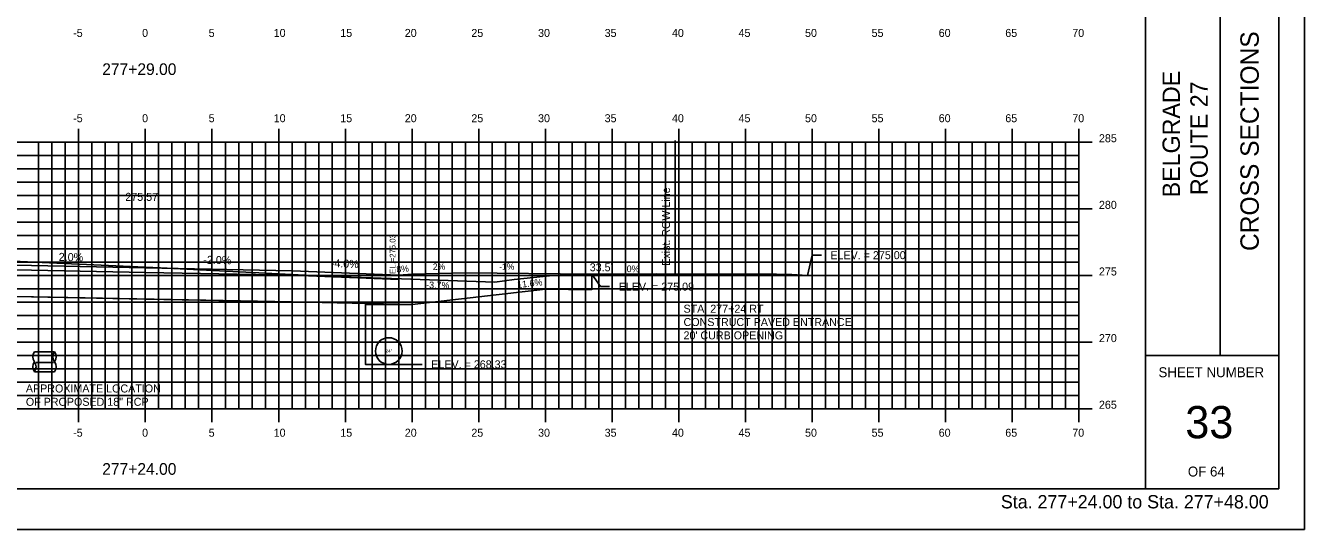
# Model space of a CAD drawing. Extents: x 854231 to 854401, y 366268 to 366378.
# Drawn here: x 854304.8 to 854400.7, y 366268.2 to 366306 of the extents above; entities that cross this region are included whole.
import ezdxf

# ---------------------------------------------------------------- set-up
doc = ezdxf.new("R2010")
doc.units = 0
for name, color, linetype in [('ANNOTATION', 7, 'Continuous'), ('BORDER', 7, 'Continuous'), ('D_Drainage_Culvert', 7, 'Continuous'), ('D_Drainage_Text', 7, 'Continuous'), ('D_Roadway_Centerline_Text', 7, 'Continuous'), ('D_Roadway_Drive_Gravel_RT', 7, 'Continuous'), ('D_Roadway_Drive_SubGrade', 7, 'Continuous'), ('D_Roadway_Edge_TW', 7, 'Continuous'), ('D_Roadway_SubGrade', 7, 'Continuous'), ('D_Text_Monospaced', 7, 'Continuous'), ('D_Text_Standard', 7, 'Continuous'), ('E_ROW_Line', 7, 'Continuous'), ('H_V ANNOTATION', 7, 'Continuous'), ('HIGHWAY_TITLE', 7, 'Continuous'), ('JUNK COM EXC', 7, 'Continuous'), ('junk strct exc', 7, 'Continuous'), ('MAJOR', 7, 'Continuous'), ('MINOR', 7, 'Continuous'), ('PDRAIN', 7, 'Continuous'), ('PLOT BOUNDARY', 7, 'Continuous'), ('S_Roadway_Centerline', 7, 'Continuous')]:
    doc.layers.add(name, color=color, linetype=linetype)

msp = doc.modelspace()

# ---------------------------------------------------------------- linework, layer by layer
at = {"layer": 'ANNOTATION'}
msp.add_line((854305.588, 366280.717), (854306.899, 366280.717), dxfattribs=at)
at = {"layer": 'BORDER'}
for p, q in [((854388.771, 366271.236), (854388.771, 366376.239)), ((854398.771, 366271.236), (854398.771, 366376.236)), ((854394.362, 366281.239), (854394.362, 366316.239)), ((854388.771, 366281.239), (854398.771, 366281.239)), ((854238.771, 366271.236), (854398.771, 366271.236))]:
    msp.add_line(p, q, dxfattribs=at)
at = {"layer": 'D_Drainage_Culvert'}
for p, q in [((854306.966, 366281.514), (854305.466, 366281.514)), ((854306.966, 366280.014), (854305.466, 366280.014))]:
    msp.add_line(p, q, dxfattribs=at)
for centre, radius, start, end in [((854305.966, 366281.139), 0.625, 143.1301, 216.8699), ((854307.466, 366281.139), 0.625, 143.1301, 216.8699), ((854306.466, 366281.139), 0.625, 323.1301, 36.8699), ((854305.966, 366280.389), 0.625, 143.1301, 216.8699), ((854304.892, 366280.389), 0.685, 326.80754, 33.19246), ((854306.466, 366280.389), 0.625, 323.1301, 36.8699)]:
    msp.add_arc(centre, radius, start, end, dxfattribs=at)
at = {"layer": 'D_Roadway_Drive_Gravel_RT'}
for p, q in [((854332.77, 366287.263), (854333.77, 366287.343)), ((854332.774, 366286.93), (854332.774, 366287.264)), ((854333.77, 366287.343), (854337.77, 366287.423)), ((854337.77, 366287.423), (854347.249, 366287.328)), ((854343.771, 366286.196), (854347.237, 366286.162))]:
    msp.add_line(p, q, dxfattribs=at)
at = {"layer": 'D_Roadway_Drive_SubGrade'}
for p, q in [((854347.249, 366287.328), (854347.249, 366286.162)), ((854333.774, 366285.07), (854343.771, 366286.196)), ((854332.774, 366285.09), (854333.774, 366285.07))]:
    msp.add_line(p, q, dxfattribs=at)
at = {"layer": 'D_Roadway_Edge_TW'}
msp.add_lwpolyline([(854294.774, 366287.703), (854302.774, 366288.023), (854324.774, 366287.583), (854332.77, 366287.263)], dxfattribs=at)
at = {"layer": 'D_Roadway_SubGrade'}
for points in [[(854302.774, 366285.69), (854302.774, 366287.69), (854313.774, 366287.47), (854324.774, 366287.25), (854324.774, 366285.25), (854313.774, 366285.47)], [(854324.774, 366287.25), (854332.774, 366286.93), (854332.774, 366285.09), (854324.774, 366285.25)]]:
    msp.add_lwpolyline(points, close=True, dxfattribs=at)
at = {"layer": 'D_Text_Standard'}
for points in [[(854363.418, 366287.232), (854363.778, 366288.759), (854364.458, 366288.759)], [(854347.249, 366287.328), (854347.906, 366286.397), (854348.586, 366286.397)], [(854333.774, 366280.566), (854333.851, 366280.566), (854334.531, 366280.566)]]:
    msp.add_lwpolyline(points, dxfattribs=at)
at = {"layer": 'E_ROW_Line'}
msp.add_line((854353.509, 366287.362), (854353.509, 366297.362), dxfattribs=at)
at = {"layer": 'JUNK COM EXC'}
msp.add_lwpolyline([(854293.772, 366288.043), (854293.774, 366285.51), (854302.774, 366285.69), (854324.774, 366285.25), (854333.774, 366285.07), (854333.77, 366286.951), (854332.973, 366286.981), (854327.686, 366287.169), (854318.367, 366287.641), (854314.902, 366287.816), (854313.222, 366287.894), (854303.833, 366288.299), (854294.211, 366288.049), (854293.772, 366288.043)], dxfattribs=at)
at = {"layer": 'junk strct exc'}
msp.add_lwpolyline([(854330.274, 366285.07), (854330.274, 366280.566), (854333.774, 366280.566), (854333.774, 366285.07)], close=True, dxfattribs=at)
at = {"layer": 'MAJOR'}
for p, q in [((854308.771, 366298.238), (854308.771, 366297.236)), ((854313.771, 366298.238), (854313.771, 366297.236)), ((854318.771, 366298.238), (854318.771, 366297.236)), ((854323.771, 366298.238), (854323.771, 366297.236)), ((854328.771, 366298.238), (854328.771, 366297.236)), ((854333.771, 366298.238), (854333.771, 366297.236)), ((854338.771, 366298.238), (854338.771, 366297.236)), ((854343.771, 366298.238), (854343.771, 366297.236)), ((854348.771, 366298.238), (854348.771, 366297.236)), ((854353.771, 366298.238), (854353.771, 366297.236)), ((854358.771, 366298.238), (854358.771, 366297.236)), ((854363.771, 366298.238), (854363.771, 366297.236)), ((854368.771, 366298.238), (854368.771, 366297.236)), ((854373.771, 366298.238), (854373.771, 366297.236)), ((854378.771, 366298.238), (854378.771, 366297.236)), ((854383.771, 366298.238), (854383.771, 366297.236)), ((854243.771, 366297.236), (854383.771, 366297.236)), ((854243.771, 366297.236), (854383.771, 366297.236)), ((854308.771, 366277.236), (854308.771, 366297.236)), ((854313.771, 366277.236), (854313.771, 366297.236)), ((854318.771, 366277.236), (854318.771, 366297.236)), ((854323.771, 366277.236), (854323.771, 366297.236)), ((854328.771, 366277.236), (854328.771, 366297.236)), ((854333.771, 366277.236), (854333.771, 366297.236)), ((854338.771, 366277.236), (854338.771, 366297.236)), ((854343.771, 366277.236), (854343.771, 366297.236)), ((854348.771, 366277.236), (854348.771, 366297.236)), ((854353.771, 366277.236), (854353.771, 366297.236)), ((854358.771, 366277.236), (854358.771, 366297.236)), ((854363.771, 366277.236), (854363.771, 366297.236)), ((854368.771, 366277.236), (854368.771, 366297.236)), ((854373.771, 366277.236), (854373.771, 366297.236)), ((854378.771, 366277.236), (854378.771, 366297.236)), ((854384.773, 366297.236), (854382.769, 366297.236)), ((854383.771, 366277.236), (854383.771, 366297.236)), ((854383.771, 366277.236), (854383.771, 366297.236)), ((854243.771, 366292.236), (854383.771, 366292.236)), ((854384.773, 366292.236), (854382.769, 366292.236)), ((854243.771, 366287.236), (854383.771, 366287.236)), ((854384.773, 366287.236), (854382.769, 366287.236)), ((854243.771, 366282.236), (854383.771, 366282.236)), ((854384.773, 366282.236), (854382.769, 366282.236)), ((854243.771, 366277.236), (854383.771, 366277.236)), ((854243.771, 366277.236), (854383.771, 366277.236)), ((854308.771, 366276.234), (854308.771, 366277.236)), ((854313.771, 366276.234), (854313.771, 366277.236)), ((854318.771, 366276.234), (854318.771, 366277.236)), ((854323.771, 366276.234), (854323.771, 366277.236)), ((854328.771, 366276.234), (854328.771, 366277.236)), ((854333.771, 366276.234), (854333.771, 366277.236)), ((854338.771, 366276.234), (854338.771, 366277.236)), ((854343.771, 366276.234), (854343.771, 366277.236)), ((854348.771, 366276.234), (854348.771, 366277.236)), ((854353.771, 366276.234), (854353.771, 366277.236)), ((854358.771, 366276.234), (854358.771, 366277.236)), ((854363.771, 366276.234), (854363.771, 366277.236)), ((854368.771, 366276.234), (854368.771, 366277.236)), ((854373.771, 366276.234), (854373.771, 366277.236)), ((854378.771, 366276.234), (854378.771, 366277.236)), ((854384.773, 366277.236), (854382.769, 366277.236)), ((854383.771, 366276.234), (854383.771, 366277.236))]:
    msp.add_line(p, q, dxfattribs=at)
at = {"layer": 'MINOR'}
for p, q in [((854305.771, 366277.236), (854305.771, 366297.236)), ((854306.771, 366277.236), (854306.771, 366297.236)), ((854306.771, 366277.236), (854306.771, 366297.236)), ((854307.771, 366277.236), (854307.771, 366297.236)), ((854309.771, 366277.236), (854309.771, 366297.236)), ((854310.771, 366277.236), (854310.771, 366297.236)), ((854311.771, 366277.236), (854311.771, 366297.236)), ((854312.771, 366277.236), (854312.771, 366297.236)), ((854314.771, 366277.236), (854314.771, 366297.236)), ((854315.771, 366277.236), (854315.771, 366297.236)), ((854316.771, 366277.236), (854316.771, 366297.236)), ((854317.771, 366277.236), (854317.771, 366297.236)), ((854319.771, 366277.236), (854319.771, 366297.236)), ((854320.771, 366277.236), (854320.771, 366297.236)), ((854321.771, 366277.236), (854321.771, 366297.236)), ((854322.771, 366277.236), (854322.771, 366297.236)), ((854324.771, 366277.236), (854324.771, 366297.236)), ((854325.771, 366277.236), (854325.771, 366297.236)), ((854326.771, 366277.236), (854326.771, 366297.236)), ((854327.771, 366277.236), (854327.771, 366297.236)), ((854329.771, 366277.236), (854329.771, 366297.236)), ((854330.771, 366277.236), (854330.771, 366297.236)), ((854331.771, 366277.236), (854331.771, 366297.236)), ((854332.771, 366277.236), (854332.771, 366297.236)), ((854334.771, 366277.236), (854334.771, 366297.236)), ((854335.771, 366277.236), (854335.771, 366297.236)), ((854336.771, 366277.236), (854336.771, 366297.236)), ((854337.771, 366277.236), (854337.771, 366297.236)), ((854339.771, 366277.236), (854339.771, 366297.236)), ((854340.771, 366277.236), (854340.771, 366297.236)), ((854341.771, 366277.236), (854341.771, 366297.236)), ((854342.771, 366277.236), (854342.771, 366297.236)), ((854344.771, 366277.236), (854344.771, 366297.236)), ((854345.771, 366277.236), (854345.771, 366297.236)), ((854346.771, 366277.236), (854346.771, 366297.236)), ((854347.771, 366277.236), (854347.771, 366297.236)), ((854349.771, 366277.236), (854349.771, 366297.236)), ((854350.771, 366277.236), (854350.771, 366297.236)), ((854351.771, 366277.236), (854351.771, 366297.236)), ((854352.771, 366277.236), (854352.771, 366297.236)), ((854354.771, 366277.236), (854354.771, 366297.236)), ((854355.771, 366277.236), (854355.771, 366297.236)), ((854356.771, 366277.236), (854356.771, 366297.236)), ((854357.771, 366277.236), (854357.771, 366297.236)), ((854359.771, 366277.236), (854359.771, 366297.236)), ((854360.771, 366277.236), (854360.771, 366297.236)), ((854361.771, 366277.236), (854361.771, 366297.236)), ((854362.771, 366277.236), (854362.771, 366297.236)), ((854364.771, 366277.236), (854364.771, 366297.236)), ((854365.771, 366277.236), (854365.771, 366297.236)), ((854366.771, 366277.236), (854366.771, 366297.236)), ((854367.771, 366277.236), (854367.771, 366297.236)), ((854369.771, 366277.236), (854369.771, 366297.236)), ((854370.771, 366277.236), (854370.771, 366297.236)), ((854371.771, 366277.236), (854371.771, 366297.236)), ((854372.771, 366277.236), (854372.771, 366297.236)), ((854374.771, 366277.236), (854374.771, 366297.236)), ((854375.771, 366277.236), (854375.771, 366297.236)), ((854376.771, 366277.236), (854376.771, 366297.236)), ((854377.771, 366277.236), (854377.771, 366297.236)), ((854379.771, 366277.236), (854379.771, 366297.236)), ((854380.771, 366277.236), (854380.771, 366297.236)), ((854381.771, 366277.236), (854381.771, 366297.236)), ((854382.771, 366277.236), (854382.771, 366297.236)), ((854243.771, 366296.236), (854383.771, 366296.236)), ((854383.771, 366296.236), (854382.769, 366296.236)), ((854243.771, 366295.236), (854383.771, 366295.236)), ((854383.771, 366295.236), (854382.769, 366295.236)), ((854243.771, 366294.236), (854383.771, 366294.236)), ((854383.771, 366294.236), (854382.769, 366294.236)), ((854243.771, 366293.236), (854383.771, 366293.236)), ((854383.771, 366293.236), (854382.769, 366293.236)), ((854243.771, 366291.236), (854383.771, 366291.236)), ((854383.771, 366291.236), (854382.769, 366291.236)), ((854243.771, 366290.236), (854383.771, 366290.236)), ((854383.771, 366290.236), (854382.769, 366290.236)), ((854243.771, 366289.236), (854383.771, 366289.236)), ((854383.771, 366289.236), (854382.769, 366289.236)), ((854243.771, 366288.236), (854383.771, 366288.236)), ((854383.771, 366288.236), (854382.769, 366288.236)), ((854243.771, 366286.236), (854383.771, 366286.236)), ((854383.771, 366286.236), (854382.769, 366286.236)), ((854243.771, 366285.236), (854383.771, 366285.236)), ((854383.771, 366285.236), (854382.769, 366285.236)), ((854243.771, 366284.236), (854383.771, 366284.236)), ((854383.771, 366284.236), (854382.769, 366284.236)), ((854243.771, 366283.236), (854383.771, 366283.236)), ((854383.771, 366283.236), (854382.769, 366283.236)), ((854243.771, 366281.236), (854383.771, 366281.236)), ((854383.771, 366281.236), (854382.769, 366281.236)), ((854243.771, 366280.236), (854383.771, 366280.236)), ((854383.771, 366280.236), (854382.769, 366280.236)), ((854243.771, 366279.236), (854383.771, 366279.236)), ((854383.771, 366279.236), (854382.769, 366279.236)), ((854243.771, 366278.236), (854383.771, 366278.236)), ((854383.771, 366278.236), (854382.769, 366278.236))]:
    msp.add_line(p, q, dxfattribs=at)
at = {"layer": 'PDRAIN'}
msp.add_lwpolyline([(854330.274, 366285.14), (854330.274, 366280.566), (854333.774, 366280.566), (854333.774, 366285.07)], dxfattribs=at)
msp.add_circle((854332.024, 366281.566), 1, dxfattribs=at)
at = {"layer": 'PLOT BOUNDARY'}
msp.add_lwpolyline([(854230.678, 366268.177), (854400.678, 366268.177), (854400.678, 366378.177), (854230.678, 366378.177)], close=True, dxfattribs=at)
at = {"layer": 'S_Roadway_Centerline'}
msp.add_lwpolyline([(854303.833, 366288.299), (854313.222, 366287.894), (854314.902, 366287.816), (854318.367, 366287.641), (854327.686, 366287.169), (854332.973, 366286.981), (854339.984, 366286.724), (854341.439, 366286.923), (854344.319, 366287.228), (854346.684, 366287.324), (854352.088, 366287.37), (854361.09, 366287.323), (854362.245, 366287.298), (854363.418, 366287.232)], dxfattribs=at)

# ---------------------------------------------------------------- texts
at = {"layer": 'ANNOTATION'}
for s, rotation, p in [('2.0%', 358.85423, (854307.277, 366288.334)), ('-2.0%', 358.85423, (854318.117, 366288.117)), ('-4.0%', 357.70942, (854327.667, 366287.869))]:
    msp.add_text(s, height=0.6, rotation=rotation, dxfattribs=at).set_placement(p)
for s, p in [('STA. 277+24 RT', (854354.125, 366284.441)), ('CONSTRUCT PAVED ENTRANCE', (854354.125, 366283.441)), ("20' CURB OPENING", (854354.125, 366282.441))]:
    msp.add_text(s, height=0.6, dxfattribs=at).set_placement(p)
at = {"layer": 'BORDER'}
for s, height, rotation, p in [('CROSS SECTIONS', 1.37787, 90, (854397.255, 366289.073)), ('SHEET NUMBER', 0.74527, 360, (854389.736, 366279.603)), ('33', 2.4194, 360, (854391.747, 366275.019)), ('OF 64', 0.7453, 360, (854391.938, 366272.149))]:
    msp.add_text(s, height=height, rotation=rotation, dxfattribs=at).set_placement(p)
at = {"layer": 'D_Drainage_Text'}
for s, p in [('APPROXIMATE LOCATION', (854304.815, 366278.456)), ('OF PROPOSED 18" RCP', (854304.815, 366277.456))]:
    msp.add_text(s, height=0.6, dxfattribs=at).set_placement(p)
at = {"layer": 'D_Roadway_Centerline_Text'}
msp.add_text('275.57', height=0.6, dxfattribs=at).set_placement((854312.272, 366292.835))
at = {"layer": 'D_Roadway_Drive_Gravel_RT'}
for s, rotation, p in [('8%', 4.57392, (854332.617, 366287.457)), ('2%', 1.19222, (854335.332, 366287.652))]:
    msp.add_text(s, height=0.48, rotation=rotation, dxfattribs=at).set_placement(p)
msp.add_text('-1%', height=0.48, dxfattribs=at).set_placement((854340.299, 366287.663))
at = {"layer": 'D_Text_Monospaced'}
for s, rotation, p in [('0%', 359.62651, (854349.861, 366287.486)), ('11.6%', 6.2166, (854341.681, 366286.289)), ('-3.7%', 358.69433, (854334.824, 366286.286))]:
    msp.add_text(s, height=0.5, rotation=rotation, dxfattribs=at).set_placement(p)
at = {"layer": 'D_Text_Standard'}
msp.add_text(' EL.=275.03', height=0.4335, rotation=90, dxfattribs=at).set_placement((854332.528, 366287.194))
for s, p in [('ELEV. = 275.00', (854365.138, 366288.459)), ("33.5'", (854347.093, 366287.551)), ('ELEV. = 275.09', (854349.266, 366286.097)), ('ELEV. = 268.33', (854335.211, 366280.266))]:
    msp.add_text(s, height=0.6, dxfattribs=at).set_placement(p)
at = {"layer": 'E_ROW_Line'}
msp.add_text('Exist. ROW Line', height=0.6, rotation=90, dxfattribs=at).set_placement((854353.109, 366287.962))
at = {"layer": 'H_V ANNOTATION'}
for s, height, p in [('-5', 0.6, (854308.361, 366305.136)), ('0', 0.6, (854313.53, 366305.136)), ('5', 0.6, (854318.522, 366305.136)), ('10', 0.6, (854323.396, 366305.136)), ('15', 0.6, (854328.388, 366305.136)), ('20', 0.6, (854333.225, 366305.136)), ('25', 0.6, (854338.217, 366305.136)), ('30', 0.6, (854343.219, 366305.136)), ('35', 0.6, (854348.211, 366305.136)), ('40', 0.6, (854353.257, 366305.136)), ('45', 0.6, (854358.249, 366305.136)), ('50', 0.6, (854363.235, 366305.136)), ('55', 0.6, (854368.227, 366305.136)), ('60', 0.6, (854373.257, 366305.136)), ('65', 0.6, (854378.249, 366305.136)), ('70', 0.6, (854383.273, 366305.136)), ('277+29.00', 0.875, (854310.54, 366302.28)), ('-5', 0.6, (854308.361, 366298.736)), ('0', 0.6, (854313.53, 366298.736)), ('5', 0.6, (854318.522, 366298.736)), ('10', 0.6, (854323.396, 366298.736)), ('15', 0.6, (854328.388, 366298.736)), ('20', 0.6, (854333.225, 366298.736)), ('25', 0.6, (854338.217, 366298.736)), ('30', 0.6, (854343.219, 366298.736)), ('35', 0.6, (854348.211, 366298.736)), ('40', 0.6, (854353.257, 366298.736)), ('45', 0.6, (854358.249, 366298.736)), ('50', 0.6, (854363.235, 366298.736)), ('55', 0.6, (854368.227, 366298.736)), ('60', 0.6, (854373.257, 366298.736)), ('65', 0.6, (854378.249, 366298.736)), ('70', 0.6, (854383.273, 366298.736)), ('285', 0.6, (854385.271, 366297.236)), ('280', 0.6, (854385.271, 366292.236)), ('275', 0.6, (854385.271, 366287.236)), ('270', 0.6, (854385.271, 366282.236)), ('265', 0.6, (854385.271, 366277.236)), ('-5', 0.6, (854308.361, 366275.136)), ('0', 0.6, (854313.53, 366275.136)), ('5', 0.6, (854318.522, 366275.136)), ('10', 0.6, (854323.396, 366275.136)), ('15', 0.6, (854328.388, 366275.136)), ('20', 0.6, (854333.225, 366275.136)), ('25', 0.6, (854338.217, 366275.136)), ('30', 0.6, (854343.219, 366275.136)), ('35', 0.6, (854348.211, 366275.136)), ('40', 0.6, (854353.257, 366275.136)), ('45', 0.6, (854358.249, 366275.136)), ('50', 0.6, (854363.235, 366275.136)), ('55', 0.6, (854368.227, 366275.136)), ('60', 0.6, (854373.257, 366275.136)), ('65', 0.6, (854378.249, 366275.136)), ('70', 0.6, (854383.273, 366275.136)), ('277+24.00', 0.875, (854310.54, 366272.28)), ('Sta. 277+24.00 to Sta. 277+48.00', 1.0002, (854377.917, 366269.756))]:
    msp.add_text(s, height=height, dxfattribs=at).set_placement(p)
at = {"layer": 'HIGHWAY_TITLE'}
for s, p in [('BELGRADE', (854391.343, 366293.095)), ('ROUTE 27', (854393.43, 366293.269))]:
    msp.add_text(s, height=1.3043, rotation=90, dxfattribs=at).set_placement(p)
at = {"layer": 'PDRAIN'}
msp.add_text('24"', height=0.25, dxfattribs=at).set_placement((854331.782, 366281.441))
at = {"layer": 'S_Roadway_Centerline'}
for s, p in [('C', (854314.897, 366287.816)), ('L', (854314.902, 366287.809))]:
    msp.add_text(s, height=0.0146, dxfattribs=at).set_placement(p)

doc.saveas('drawing.dxf')
